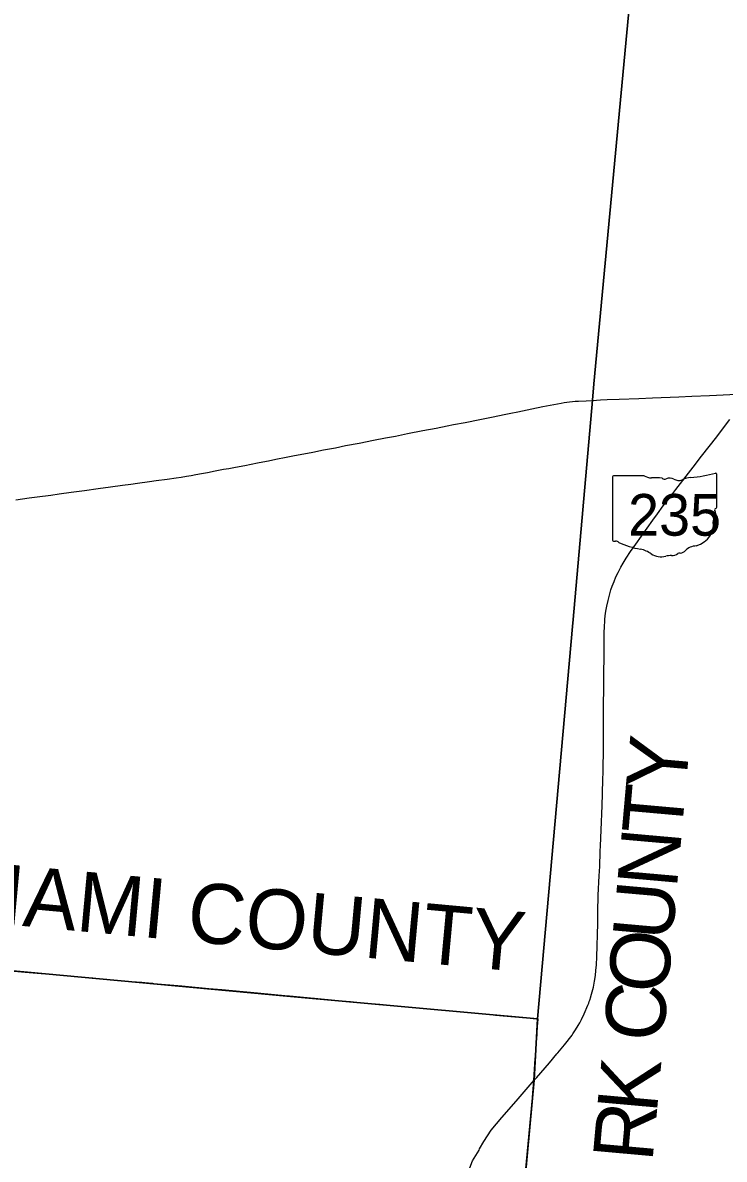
# Model space of a CAD drawing. Extents: x 0 to 34, y 0 to 22.
# Drawn here: x 5.8104 to 5.9988, y 15.8236 to 16.1285 of the extents above; entities that cross this region are included whole.
import ezdxf

# ---------------------------------------------------------------- set-up
doc = ezdxf.new("R2010")
doc.units = 0
for name, color, linetype in [('GM_X_Corporation', 7, 'Continuous'), ('GM_X_County', 7, 'Continuous'), ('GM_X_County_Text', 7, 'Continuous'), ('GM_X_State_Location', 7, 'Continuous'), ('GM_X_State_Route', 7, 'Continuous'), ('GM_X_State_Shield', 7, 'Continuous'), ('GM_X_US_Route', 7, 'Continuous')]:
    doc.layers.add(name, color=color, linetype=linetype)

msp = doc.modelspace()

# ---------------------------------------------------------------- linework, layer by layer
at = {"layer": 'GM_X_Corporation'}
msp.add_lwpolyline([(5.801956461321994, 15.874609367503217), (5.811052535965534, 15.873807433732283), (5.815423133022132, 15.873422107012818), (5.817908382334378, 15.8732030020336), (5.821419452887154, 15.872893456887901), (5.829226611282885, 15.872205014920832), (5.830345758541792, 15.872106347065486), (5.837598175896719, 15.871466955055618), (5.839647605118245, 15.871286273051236), (5.842430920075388, 15.87104088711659), (5.843200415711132, 15.870973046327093), (5.845266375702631, 15.870790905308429), (5.845504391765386, 15.870769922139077), (5.8531059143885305, 15.870099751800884), (5.860379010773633, 15.869418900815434), (5.863864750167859, 15.869092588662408), (5.873485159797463, 15.86819200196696), (5.880807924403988, 15.867506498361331), (5.881435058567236, 15.867447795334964), (5.8820829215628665, 15.867387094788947), (5.888713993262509, 15.866766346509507), (5.888791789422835, 15.866759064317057), (5.8951087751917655, 15.8661677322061), (5.898316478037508, 15.865867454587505), (5.898394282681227, 15.865860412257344), (5.902638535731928, 15.865476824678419), (5.902718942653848, 15.865469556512), (5.906315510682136, 15.865144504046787), (5.9099996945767, 15.864803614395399), (5.910071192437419, 15.86479700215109), (5.91377635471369, 15.864454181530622), (5.9138491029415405, 15.864447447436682), (5.917579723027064, 15.86410227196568), (5.917650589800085, 15.86409571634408), (5.9214111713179, 15.863747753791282), (5.921477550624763, 15.863741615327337), (5.925266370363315, 15.863391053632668), (5.925331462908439, 15.863385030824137), (5.928883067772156, 15.863056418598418), (5.928946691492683, 15.863050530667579), (5.933226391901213, 15.862654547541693), (5.933284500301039, 15.862649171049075), (5.93730541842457, 15.862277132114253), (5.93734949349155, 15.862273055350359), (5.941447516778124, 15.86189388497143), (5.941460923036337, 15.861892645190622), (5.945656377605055, 15.861504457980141), (5.945766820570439, 15.861494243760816), (5.9483604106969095, 15.861254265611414), (5.948721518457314, 15.86122085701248), (5.9487159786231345, 15.86114468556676), (5.94857179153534, 15.859161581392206), (5.948563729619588, 15.859050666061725), (5.948457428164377, 15.85758867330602), (5.948420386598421, 15.857079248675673), (5.948127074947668, 15.853045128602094), (5.947968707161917, 15.850866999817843), (5.947954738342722, 15.850674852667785), (5.947950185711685, 15.850612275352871), (5.947633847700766, 15.846261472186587), (5.94761544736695, 15.846008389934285), (5.947609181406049, 15.845922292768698), (5.947464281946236, 15.84392934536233), (5.947440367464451, 15.843600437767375), (5.94743552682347, 15.843533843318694), (5.947277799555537, 15.841364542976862), (5.9471804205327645, 15.840025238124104), (5.945149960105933, 15.81822605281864)], dxfattribs=at)
at = {"layer": 'GM_X_County'}
for points in [[(5.978469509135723, 16.187855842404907), (5.963740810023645, 16.031605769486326), (5.963377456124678, 16.02723393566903), (5.958190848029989, 15.9684008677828), (5.958060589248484, 15.966508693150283), (5.948614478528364, 15.861268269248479), (5.881362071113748, 15.86734137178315), (5.736215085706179, 15.880751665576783), (5.735794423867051, 15.88079120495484), (5.682290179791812, 15.885820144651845), (5.653672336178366, 15.888443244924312), (5.6129720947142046, 15.892484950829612)], [(6.3866363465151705, 15.646992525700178), (6.234638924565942, 15.661300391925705), (6.222991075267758, 15.662398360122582), (6.205680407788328, 15.664031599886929), (6.204747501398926, 15.664121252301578), (6.203003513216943, 15.66428578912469), (6.201742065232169, 15.664416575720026), (6.193030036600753, 15.665228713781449), (6.068689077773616, 15.676965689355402), (6.011145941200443, 15.683010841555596), (5.933465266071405, 15.6905226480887), (5.935810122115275, 15.717000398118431), (5.94103628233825, 15.771032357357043), (5.941395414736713, 15.77478506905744), (5.941476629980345, 15.77546958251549), (5.941600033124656, 15.776793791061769), (5.942146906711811, 15.783645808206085), (5.947758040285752, 15.844796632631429), (5.948614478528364, 15.861268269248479), (5.958060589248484, 15.966508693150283), (5.958190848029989, 15.9684008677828), (5.963377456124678, 16.02723393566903), (5.963740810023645, 16.031605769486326), (5.978469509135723, 16.187855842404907)], [(5.6129720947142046, 15.892484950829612), (5.653672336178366, 15.888443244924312), (5.682290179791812, 15.885820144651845), (5.735794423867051, 15.88079120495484), (5.736215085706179, 15.880751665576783), (5.881362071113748, 15.86734137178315), (5.948614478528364, 15.861268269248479), (5.947758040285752, 15.844796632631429), (5.942146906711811, 15.783645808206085)]]:
    msp.add_lwpolyline(points, dxfattribs=at)
at = {"layer": 'GM_X_State_Route'}
for points in [[(5.968716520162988, 15.977352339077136), (5.9691827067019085, 15.978605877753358), (5.969688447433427, 15.979819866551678), (5.970247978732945, 15.981009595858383), (5.970983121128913, 15.982407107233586), (5.971637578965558, 15.983548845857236), (5.972476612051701, 15.98488676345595), (5.973645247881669, 15.986641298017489), (5.975012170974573, 15.98857935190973), (5.979589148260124, 15.995032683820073), (5.98081051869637, 15.996750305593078), (5.982382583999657, 15.998865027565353), (5.98414608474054, 16.001165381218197), (5.985762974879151, 16.0032495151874), (5.990430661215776, 16.009305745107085), (5.992700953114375, 16.012216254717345), (5.996746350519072, 16.017424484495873), (5.999141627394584, 16.020576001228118), (6.0002790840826, 16.02208425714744)], [(5.9664200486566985, 15.95080326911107), (5.966436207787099, 15.953009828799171), (5.966490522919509, 15.95934872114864), (5.966522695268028, 15.964363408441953), (5.96653956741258, 15.964875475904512), (5.966592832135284, 15.966470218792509), (5.966697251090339, 15.968045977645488), (5.966731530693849, 15.968370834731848), (5.96683383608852, 15.969353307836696), (5.967023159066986, 15.970653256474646), (5.967263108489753, 15.971945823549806), (5.967604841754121, 15.973486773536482), (5.967956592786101, 15.974908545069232), (5.9681390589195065, 15.975638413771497), (5.968356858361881, 15.97638304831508), (5.968716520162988, 15.977352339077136)], [(5.964962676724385, 15.894346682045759), (5.9649648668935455, 15.894430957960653), (5.96519848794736, 15.899601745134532), (5.965331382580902, 15.902098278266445), (5.9653814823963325, 15.903521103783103), (5.96542419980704, 15.904738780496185), (5.9654906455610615, 15.906199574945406), (5.965556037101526, 15.907641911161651), (5.965724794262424, 15.911865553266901), (5.965974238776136, 15.918464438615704), (5.966061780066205, 15.92158378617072), (5.966096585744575, 15.922469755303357), (5.9661867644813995, 15.92475112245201), (5.966265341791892, 15.928184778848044), (5.966323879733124, 15.933587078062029), (5.9663307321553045, 15.934257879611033), (5.9663781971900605, 15.940859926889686), (5.966386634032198, 15.942974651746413), (5.966394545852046, 15.944188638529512), (5.966398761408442, 15.944820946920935), (5.9664188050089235, 15.95063353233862), (5.9664200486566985, 15.95080326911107)], [(5.962950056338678, 15.86714304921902), (5.962975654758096, 15.867220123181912), (5.963330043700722, 15.868489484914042), (5.963633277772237, 15.86977202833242), (5.963935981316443, 15.871323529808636), (5.964180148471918, 15.87288504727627), (5.964332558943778, 15.874193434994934), (5.964457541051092, 15.875768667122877), (5.964556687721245, 15.877871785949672), (5.964806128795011, 15.886808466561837), (5.964833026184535, 15.888387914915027), (5.964848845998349, 15.889964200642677), (5.964962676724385, 15.894346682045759)], [(5.960019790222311, 15.86019513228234), (5.960092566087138, 15.860309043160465), (5.960438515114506, 15.861049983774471), (5.961155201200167, 15.862542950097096), (5.962175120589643, 15.864889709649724), (5.962388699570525, 15.865474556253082), (5.962543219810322, 15.865898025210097), (5.962642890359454, 15.8662181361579), (5.962950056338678, 15.86714304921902)], [(5.954074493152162, 15.852102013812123), (5.955864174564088, 15.85425386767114), (5.957901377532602, 15.856848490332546), (5.958128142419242, 15.857178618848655), (5.958850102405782, 15.858290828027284), (5.959530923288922, 15.859425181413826), (5.960019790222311, 15.86019513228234)], [(5.947777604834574, 15.844751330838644), (5.948370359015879, 15.845441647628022), (5.951826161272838, 15.849413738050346), (5.953857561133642, 15.851841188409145), (5.954074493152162, 15.852102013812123)], [(5.933105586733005, 15.826321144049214), (5.934242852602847, 15.828286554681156), (5.93621465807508, 15.831347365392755), (5.93908351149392, 15.834746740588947), (5.9428805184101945, 15.83911857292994), (5.947777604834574, 15.844751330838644)], [(5.9291923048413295, 15.817940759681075), (5.931218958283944, 15.823114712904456), (5.9329371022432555, 15.826029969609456), (5.933105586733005, 15.826321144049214)]]:
    msp.add_lwpolyline(points, dxfattribs=at)
at = {"layer": 'GM_X_State_Shield'}
for p, q in [((5.968779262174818, 16.006670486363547), (5.968779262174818, 15.989686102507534)), ((5.977246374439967, 16.00696271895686), (5.969054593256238, 16.00696271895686)), ((5.996751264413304, 15.99849887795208), (5.996751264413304, 16.00738362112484)), ((5.996748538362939, 15.998501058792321), (5.996751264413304, 15.99849887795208))]:
    msp.add_line(p, q, dxfattribs=at)
for centre, major_axis, ratio, start_param, end_param in [((5.986787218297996, 16.03011822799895), (0.029664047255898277, 0), 0.7999999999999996, 4.81439421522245, 5.042368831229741), ((5.996441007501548, 16.007420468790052), (0.00031139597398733, 0), 0.8000000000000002, 6.141151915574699, 7.989035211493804), ((5.969099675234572, 16.006706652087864), (0.00032405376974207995, 0), 0.7999999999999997, 1.7126933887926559, 3.283489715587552), ((5.979197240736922, 16.008934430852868), (0.0031431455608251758, 0), 0.8000000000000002, 4.042522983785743, 4.731795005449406), ((5.9802393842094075, 15.9974274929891), (0.011283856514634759, 0), 0.7999999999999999, 1.4047577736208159, 1.6578580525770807), ((5.982801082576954, 16.006794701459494), (0.0009067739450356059, 0), 0.8, 3.836095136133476, 5.185414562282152), ((5.984132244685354, 16.00483163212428), (0.001885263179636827, 0), 0.8000000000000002, 0.9506229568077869, 2.0794050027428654), ((5.986565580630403, 16.007524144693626), (0.0022679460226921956, 0), 0.8, 4.0815607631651, 5.145722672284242), ((5.990570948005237, 16.001775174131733), (0.005967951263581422, 0), 0.8000000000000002, 1.6990113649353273, 2.107814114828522), ((5.996419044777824, 15.9984645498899), (0.0003332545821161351, 0), 0.8, 5.054540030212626, 6.418171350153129), ((5.997866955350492, 15.994780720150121), (0.0021047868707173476, 0), 0.7999999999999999, 2.3877238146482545, 3.2625368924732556), ((5.9966793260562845, 15.997846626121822), (0.0004819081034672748, 0), 0.8000000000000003, 1.8839779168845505, 3.671072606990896), ((5.993613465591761, 15.996723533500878), (0.00289289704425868, 0), 0.8, 5.934694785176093, 6.69594811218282), ((5.988448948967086, 15.993650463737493), (0.007419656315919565, 0), 0.8000000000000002, 5.1017524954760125, 6.440017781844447), ((5.969102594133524, 15.98964892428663), (0.00032693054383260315, 0), 0.7999999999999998, 3.0012400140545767, 4.508300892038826), ((5.96915216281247, 15.99138656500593), (0.0024948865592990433, 0), 0.8, 4.6659456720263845, 4.897461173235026), ((5.969662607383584, 15.988706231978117), (0.0008996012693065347, 0), 0.8000000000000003, 0.5192071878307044, 1.6278990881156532), ((5.981020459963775, 16.003965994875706), (0.02142156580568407, 0), 0.7999999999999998, 4.195997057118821, 4.488960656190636), ((5.974633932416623, 15.982055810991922), (0.006702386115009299, 0), 0.8, 0.8235188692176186, 1.3235874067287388), ((5.984651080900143, 15.98735005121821), (0.002266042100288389, 0), 0.8, 4.691043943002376, 5.507373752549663), ((5.9867009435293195, 15.985705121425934), (0.000637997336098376, 0), 0.8000000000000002, 1.1475841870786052, 2.315151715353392), ((5.986428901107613, 15.988039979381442), (0.002397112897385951, 0), 0.8000000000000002, 4.93706856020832, 5.642249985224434), ((5.9915774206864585, 15.984917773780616), (0.004063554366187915, 0), 0.8000000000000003, 1.6476453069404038, 2.4884337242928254), ((5.981882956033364, 15.988621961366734), (0.004253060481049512, 0), 0.8000000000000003, 4.0264810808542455, 4.996735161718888), ((5.984340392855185, 15.9827497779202), (0.003494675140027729, 0), 0.7999999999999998, 1.4956620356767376, 1.9409797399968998)]:
    msp.add_ellipse(centre, major_axis=major_axis, ratio=ratio, start_param=start_param, end_param=end_param, dxfattribs=at)
at = {"layer": 'GM_X_US_Route'}
for points in [[(5.996654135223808, 16.028569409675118), (6.000314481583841, 16.028728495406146), (6.004417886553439, 16.028918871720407), (6.004806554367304, 16.028936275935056)], [(5.808584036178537, 16.00053623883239), (5.81214162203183, 16.001000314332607), (5.814283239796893, 16.001283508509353), (5.817937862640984, 16.001796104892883), (5.820234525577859, 16.00211252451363), (5.823471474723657, 16.00256131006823), (5.827017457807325, 16.00304437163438), (5.83067366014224, 16.003539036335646), (5.834016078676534, 16.00399309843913), (5.837186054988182, 16.004429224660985), (5.839486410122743, 16.00472929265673), (5.84120771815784, 16.00497504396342), (5.844446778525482, 16.00542541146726), (5.846223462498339, 16.005665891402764), (5.849200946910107, 16.006068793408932), (5.8516537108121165, 16.006422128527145), (5.853008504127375, 16.00662252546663), (5.854360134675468, 16.00683821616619), (5.8556890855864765, 16.007059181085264), (5.856905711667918, 16.007269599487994), (5.858403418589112, 16.007547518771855), (5.860013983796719, 16.007859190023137), (5.8620865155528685, 16.00824522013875), (5.864363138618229, 16.00869031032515), (5.865762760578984, 16.008951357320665), (5.8675257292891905, 16.0092751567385), (5.87005707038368, 16.009759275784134), (5.873434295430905, 16.010435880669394), (5.875848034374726, 16.010882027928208), (5.876375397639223, 16.010986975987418), (5.878387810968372, 16.01138724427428), (5.881132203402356, 16.011915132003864), (5.883410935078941, 16.012361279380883), (5.885880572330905, 16.01283590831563), (5.888322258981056, 16.01331000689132), (5.891222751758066, 16.013881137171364), (5.894363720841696, 16.014496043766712), (5.89712657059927, 16.01504027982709), (5.9007400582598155, 16.015745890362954), (5.904567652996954, 16.016493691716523), (5.907786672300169, 16.017105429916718), (5.910502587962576, 16.01763068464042), (5.913772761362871, 16.018263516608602), (5.917838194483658, 16.01907407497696), (5.921405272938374, 16.019756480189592), (5.92435955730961, 16.0203381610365), (5.9261172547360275, 16.020693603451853), (5.929170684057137, 16.021291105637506), (5.933152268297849, 16.022082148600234), (5.936306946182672, 16.022704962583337), (5.940116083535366, 16.02348176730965), (5.941510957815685, 16.02376443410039), (5.943353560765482, 16.02413780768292), (5.947120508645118, 16.024891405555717), (5.950103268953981, 16.0255121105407), (5.952998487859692, 16.026104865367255), (5.954009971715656, 16.026300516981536), (5.954944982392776, 16.02646769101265), (5.955803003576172, 16.02660744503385), (5.956528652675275, 16.0267261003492), (5.957261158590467, 16.0268168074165), (5.9580353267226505, 16.02688641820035), (5.958788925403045, 16.02693546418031), (5.959612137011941, 16.02697712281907), (5.961684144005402, 16.02709578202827), (5.963397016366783, 16.027188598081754)], [(5.963397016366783, 16.027188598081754), (5.965532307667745, 16.027298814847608), (5.967373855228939, 16.02738635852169), (5.9705369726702, 16.027503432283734), (5.975807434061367, 16.027705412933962), (5.979496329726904, 16.027849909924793)], [(5.979496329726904, 16.027849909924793), (5.986612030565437, 16.028153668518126), (5.990037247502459, 16.028293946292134), (5.994781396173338, 16.028488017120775), (5.996654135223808, 16.028569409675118)]]:
    msp.add_lwpolyline(points, dxfattribs=at)

# ---------------------------------------------------------------- texts
at = {"layer": 'GM_X_County_Text'}
for s, height, rotation, p in [('Y', 0.016074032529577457, 84.922325, (5.988350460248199, 15.922129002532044)), ('T', 0.016074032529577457, 84.922325, (5.9872884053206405, 15.91017525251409)), ('N', 0.016074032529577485, 84.92225600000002, (5.9860326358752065, 15.896043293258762)), ('MIAMI COUNTY', 0.016074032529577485, 354.731941, (5.786377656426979, 15.88837422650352)), ('U', 0.016074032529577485, 84.921692, (5.984776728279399, 15.881911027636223)), ('O', 0.016074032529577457, 84.915649, (5.983519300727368, 15.867777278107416)), ('C', 0.016074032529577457, 84.902412, (5.982354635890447, 15.854721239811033)), ('K', 0.01607403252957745, 84.87545, (5.9806488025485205, 15.835689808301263)), ('R', 0.016074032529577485, 84.860573, (5.979474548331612, 15.822634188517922))]:
    msp.add_text(s, height=height, rotation=rotation, dxfattribs=at).set_placement(p)
at = {"layer": 'GM_X_State_Location'}
msp.add_text('235', height=1.6074032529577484e-05, rotation=1.0000000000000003e-05, dxfattribs=at).set_placement((5.976776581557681, 15.9958797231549))
for s, p in [('s', (5.982451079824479, 15.997049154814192)), ('r', (5.982450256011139, 15.997049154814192))]:
    msp.add_text(s, height=1.6074032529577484e-05, dxfattribs=at).set_placement(p)
at = {"layer": 'GM_X_State_Shield'}
msp.add_text('235', height=0.011189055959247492, dxfattribs=at).set_placement((5.972949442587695, 15.990883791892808))

doc.saveas('drawing.dxf')
